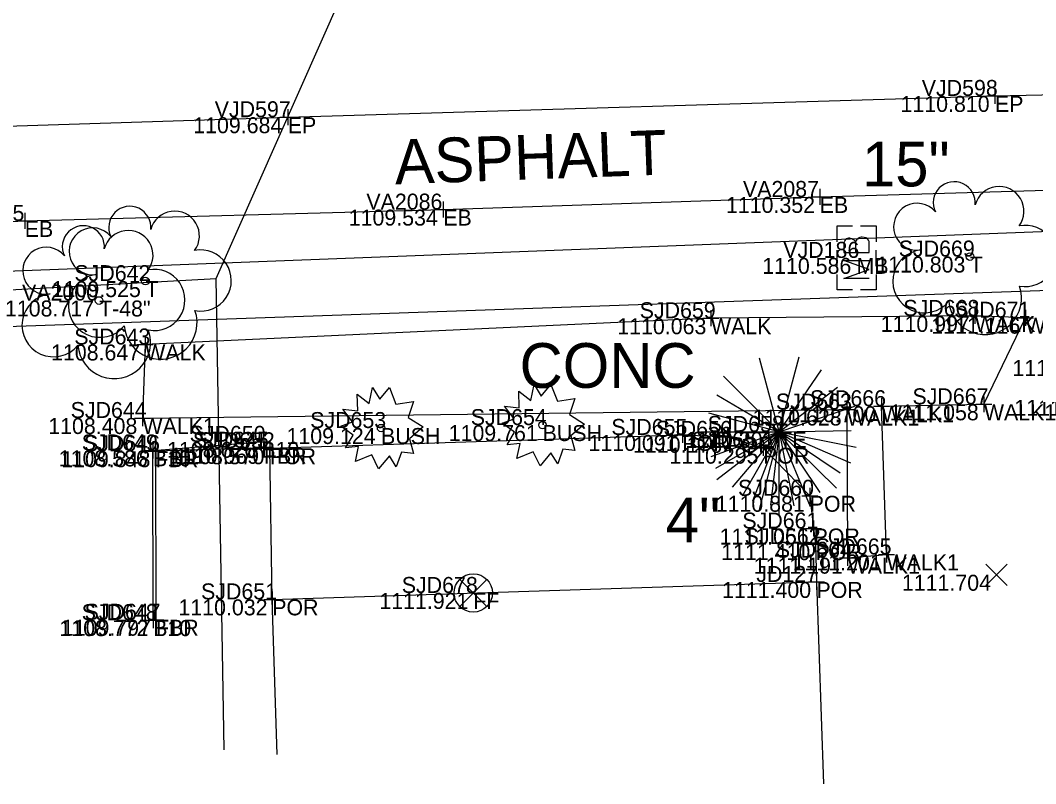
# Model space of a CAD drawing. Extents: x 1629915 to 1630675, y 484401 to 484601.
# Drawn here: x 1630425.3 to 1630488.9, y 484441.8 to 484489.5 of the extents above; entities that cross this region are included whole.
import ezdxf

# ---------------------------------------------------------------- set-up
doc = ezdxf.new("R2010")
doc.units = 0
for name, color, linetype in [('BD_X_Building', 7, 'Continuous'), ('BD_X_Porch_or_Deck', 7, 'Continuous'), ('BR_X_Sub_Foot_Object', 7, 'Continuous'), ('PV_X_EOP', 7, 'Continuous'), ('PV_X_Shoulder_Aggregate', 7, 'Continuous'), ('PV_X_Walk', 7, 'Continuous'), ('RD_X_Cells', 7, 'Continuous'), ('RD_X_RR_Cells', 7, 'Continuous'), ('SC_Scratch2', 7, 'Continuous'), ('SV_X_Break_Lines', 7, 'Continuous'), ('SV_X_Random_Point', 7, 'Continuous'), ('SV_X_Shot_Marker', 7, 'Continuous'), ('SV_X_Text_Comment', 7, 'Continuous'), ('SV_X_Text_Elevation', 7, 'Continuous'), ('SV_X_Text_Name', 7, 'Continuous'), ('TX_X_20', 7, 'Continuous'), ('UT_X_Gas', 7, 'Continuous'), ('UT_X_Water', 7, 'Continuous'), ('VG_X_Cells', 7, 'Continuous'), ('VG_X_Flower_Bed', 7, 'Continuous')]:
    doc.layers.add(name, color=color, linetype=linetype)

msp = doc.modelspace()

# ---------------------------------------------------------------- linework, layer by layer
at = {"layer": 'BD_X_Building'}
msp.add_lwpolyline([(1630441.402, 484443.574), (1630441.085, 484453.287), (1630475.163, 484454.377), (1630475.611, 484441.75)], dxfattribs=at)
at = {"layer": 'BD_X_Porch_or_Deck'}
msp.add_lwpolyline([(1630441.085, 484453.287), (1630440.931, 484462.744), (1630466.767, 484463.579), (1630469.583, 484463.459), (1630471.822, 484462.781), (1630474.739, 484459.77), (1630474.981, 484457.721), (1630475.11, 484456.743), (1630475.163, 484454.377)], dxfattribs=at)
at = {"layer": 'BR_X_Sub_Foot_Object'}
msp.add_line((1630334.981, 484467.226), (1630537.673, 484474.324), dxfattribs=at)
at = {"layer": 'PV_X_EOP'}
msp.add_lwpolyline([(1630292.708, 484478.565), (1630303.888, 484478.677), (1630360.908, 484480.855), (1630403.548, 484482.238), (1630442.06, 484483.465), (1630486.339, 484484.798), (1630529.418, 484485.732), (1630568.745, 484486.748), (1630610.183, 484487.853), (1630650.035, 484489.089)], dxfattribs=at)
at = {"layer": 'PV_X_Shoulder_Aggregate'}
msp.add_lwpolyline([(1630290.023, 484472.094), (1630316.065, 484472.69), (1630342.812, 484473.661), (1630368.021, 484474.923), (1630386.578, 484475.757), (1630401.756, 484475.856), (1630425.589, 484476.973), (1630451.796, 484477.683), (1630475.368, 484478.476), (1630505.195, 484479.358), (1630508.151, 484481.327), (1630508.061, 484484.385), (1630516.813, 484484.736), (1630516.951, 484481.103), (1630520.694, 484479.601), (1630540.986, 484479.176), (1630540.508, 484484.672), (1630564.841, 484485.646), (1630589.64, 484486.306), (1630613.109, 484486.832)], dxfattribs=at)
at = {"layer": 'PV_X_Walk'}
for p, q in [((1630468.554, 484470.882), (1630433.129, 484469.24)), ((1630485.08, 484471.029), (1630468.554, 484470.882)), ((1630488.254, 484470.917), (1630485.08, 484471.029)), ((1630485.646, 484465.495), (1630488.254, 484470.917)), ((1630433.129, 484469.24), (1630432.958, 484464.638))]:
    msp.add_line(p, q, dxfattribs=at)
msp.add_lwpolyline([(1630432.958, 484464.638), (1630477.064, 484465.169), (1630477.115, 484455.894), (1630479.551, 484456.099), (1630479.242, 484465.378), (1630485.646, 484465.495)], dxfattribs=at)
at = {"layer": 'RD_X_Cells'}
for p, q in [((1630476.45, 484474.15), (1630476.45, 484475.151)), ((1630478.893, 484474.15), (1630478.893, 484475.151)), ((1630477.671, 484474.661), (1630477.671, 484474.661))]:
    msp.add_line(p, q, dxfattribs=at)
for points in [[(1630476.45, 484475.668), (1630476.45, 484476.661), (1630477.42, 484476.661)], [(1630477.923, 484476.661), (1630478.893, 484476.661), (1630478.893, 484475.668)], [(1630477.602, 484475.683), (1630477.539, 484475.746), (1630477.501, 484475.784), (1630477.464, 484475.809), (1630477.438, 484475.821), (1630477.388, 484475.847), (1630477.35, 484475.859), (1630477.262, 484475.885), (1630477.224, 484475.885), (1630477.174, 484475.885), (1630477.098, 484475.872), (1630477.035, 484475.847), (1630476.985, 484475.809), (1630476.934, 484475.746), (1630476.909, 484475.695), (1630476.897, 484475.67), (1630476.871, 484475.607), (1630476.871, 484474.99), (1630478.471, 484474.99), (1630478.471, 484475.683), (1630478.421, 484475.771), (1630478.358, 484475.847), (1630478.257, 484475.91), (1630478.144, 484475.947), (1630478.03, 484475.96), (1630477.955, 484475.96), (1630477.879, 484475.935), (1630477.766, 484475.885), (1630477.69, 484475.821), (1630477.602, 484475.683), (1630477.602, 484474.99)], [(1630478.471, 484473.365), (1630476.871, 484473.365), (1630478.471, 484473.944), (1630476.871, 484474.499), (1630478.471, 484474.499)], [(1630477.42, 484472.661), (1630476.45, 484472.661), (1630476.45, 484473.631)], [(1630478.893, 484473.631), (1630478.893, 484472.661), (1630477.923, 484472.661)]]:
    msp.add_lwpolyline(points, dxfattribs=at)
at = {"layer": 'RD_X_RR_Cells'}
for p, q in [((1630454.521, 484452.841), (1630452.824, 484454.538)), ((1630452.824, 484452.841), (1630454.521, 484454.538))]:
    msp.add_line(p, q, dxfattribs=at)
msp.add_circle((1630453.673, 484453.689), 1.2, dxfattribs=at)
at = {"layer": 'SC_Scratch2'}
msp.add_circle((1630433.148, 484473.207), 0.24, dxfattribs=at)
for centre, radius, start, end in [((1630432.164, 484476.575), 1.317, 354.0047, 205.97412), ((1630434.974, 484476.036), 1.553, 323.82996, 165.0376), ((1630429.839, 484475.071), 1.471, 39.06254, 279.54124), ((1630436.608, 484473.243), 1.915, 259.14531, 101.45961), ((1630430.295, 484471.658), 1.974, 96.17219, 320.57371), ((1630434.095, 484470.602), 2.284, 184.94757, 19.45715)]:
    msp.add_arc(centre, radius, start, end, dxfattribs=at)
at = {"layer": 'SV_X_Break_Lines'}
msp.add_lwpolyline([(1630433.632, 484451.985), (1630433.618, 484462.612), (1630440.398, 484463.147)], dxfattribs=at)
at = {"layer": 'SV_X_Random_Point'}
for p, q in [((1630485.768, 484454.159), (1630487.101, 484455.494)), ((1630485.768, 484455.494), (1630487.101, 484454.159))]:
    msp.add_line(p, q, dxfattribs=at)
at = {"layer": 'SV_X_Shot_Marker'}
for p, q in [((1630486.339, 484485.298), (1630486.339, 484484.298)), ((1630485.839, 484484.798), (1630486.839, 484484.798)), ((1630486.339, 484484.798), (1630486.339, 484484.798)), ((1630442.06, 484483.965), (1630442.06, 484482.965)), ((1630441.56, 484483.465), (1630442.56, 484483.465)), ((1630442.06, 484483.465), (1630442.06, 484483.465)), ((1630475.368, 484478.976), (1630475.368, 484477.976)), ((1630451.796, 484478.183), (1630451.796, 484477.183)), ((1630474.868, 484478.476), (1630475.868, 484478.476)), ((1630475.368, 484478.476), (1630475.368, 484478.476)), ((1630425.589, 484477.473), (1630425.589, 484476.473)), ((1630451.296, 484477.683), (1630452.296, 484477.683)), ((1630451.796, 484477.683), (1630451.796, 484477.683)), ((1630425.089, 484476.973), (1630426.089, 484476.973)), ((1630425.589, 484476.973), (1630425.589, 484476.973)), ((1630485.08, 484471.529), (1630485.08, 484470.529)), ((1630468.054, 484470.882), (1630469.054, 484470.882)), ((1630468.554, 484471.382), (1630468.554, 484470.382)), ((1630468.554, 484470.882), (1630468.554, 484470.882)), ((1630484.58, 484471.029), (1630485.58, 484471.029)), ((1630485.08, 484471.029), (1630485.08, 484471.029)), ((1630487.754, 484470.917), (1630488.754, 484470.917)), ((1630488.254, 484471.417), (1630488.254, 484470.417)), ((1630488.254, 484470.917), (1630488.254, 484470.917)), ((1630433.129, 484469.74), (1630433.129, 484468.74)), ((1630432.629, 484469.24), (1630433.629, 484469.24)), ((1630433.129, 484469.24), (1630433.129, 484469.24)), ((1630479.242, 484465.878), (1630479.242, 484464.878)), ((1630485.646, 484465.995), (1630485.646, 484464.995)), ((1630476.564, 484465.169), (1630477.564, 484465.169)), ((1630477.064, 484465.669), (1630477.064, 484464.669)), ((1630477.064, 484465.169), (1630477.064, 484465.169)), ((1630478.742, 484465.378), (1630479.742, 484465.378)), ((1630479.242, 484465.378), (1630479.242, 484465.378)), ((1630485.146, 484465.495), (1630486.146, 484465.495)), ((1630485.646, 484465.495), (1630485.646, 484465.495)), ((1630432.458, 484464.638), (1630433.458, 484464.638)), ((1630432.958, 484465.138), (1630432.958, 484464.138)), ((1630432.958, 484464.638), (1630432.958, 484464.638)), ((1630466.767, 484464.079), (1630466.767, 484463.079)), ((1630469.583, 484463.959), (1630469.583, 484462.959)), ((1630440.398, 484463.647), (1630440.398, 484462.647)), ((1630440.563, 484463.275), (1630440.563, 484462.275)), ((1630440.931, 484463.244), (1630440.931, 484462.244)), ((1630466.267, 484463.579), (1630467.267, 484463.579)), ((1630466.767, 484463.579), (1630466.767, 484463.579)), ((1630469.083, 484463.459), (1630470.083, 484463.459)), ((1630469.583, 484463.459), (1630469.583, 484463.459)), ((1630471.822, 484463.281), (1630471.822, 484462.281)), ((1630433.118, 484462.612), (1630434.118, 484462.612)), ((1630433.618, 484463.112), (1630433.618, 484462.112)), ((1630433.618, 484462.612), (1630433.618, 484462.612)), ((1630433.777, 484463.061), (1630433.777, 484462.061)), ((1630439.898, 484463.147), (1630440.898, 484463.147)), ((1630440.063, 484462.775), (1630441.063, 484462.775)), ((1630440.398, 484463.147), (1630440.398, 484463.147)), ((1630440.431, 484462.744), (1630441.431, 484462.744)), ((1630440.563, 484462.775), (1630440.563, 484462.775)), ((1630440.931, 484462.744), (1630440.931, 484462.744)), ((1630471.322, 484462.781), (1630472.322, 484462.781)), ((1630471.822, 484462.781), (1630471.822, 484462.781)), ((1630433.277, 484462.561), (1630434.277, 484462.561)), ((1630433.777, 484462.561), (1630433.777, 484462.561)), ((1630474.739, 484460.27), (1630474.739, 484459.27)), ((1630474.239, 484459.77), (1630475.239, 484459.77)), ((1630474.739, 484459.77), (1630474.739, 484459.77)), ((1630474.981, 484458.221), (1630474.981, 484457.221)), ((1630474.481, 484457.721), (1630475.481, 484457.721)), ((1630474.981, 484457.721), (1630474.981, 484457.721)), ((1630475.11, 484457.243), (1630475.11, 484456.243)), ((1630474.61, 484456.743), (1630475.61, 484456.743)), ((1630475.11, 484456.743), (1630475.11, 484456.743)), ((1630477.115, 484456.394), (1630477.115, 484455.394)), ((1630479.551, 484456.599), (1630479.551, 484455.599)), ((1630476.615, 484455.894), (1630477.615, 484455.894)), ((1630477.115, 484455.894), (1630477.115, 484455.894)), ((1630479.051, 484456.099), (1630480.051, 484456.099)), ((1630479.551, 484456.099), (1630479.551, 484456.099)), ((1630474.663, 484454.377), (1630475.663, 484454.377)), ((1630475.163, 484454.877), (1630475.163, 484453.877)), ((1630475.163, 484454.377), (1630475.163, 484454.377)), ((1630441.085, 484453.787), (1630441.085, 484452.787)), ((1630440.585, 484453.287), (1630441.585, 484453.287)), ((1630441.085, 484453.287), (1630441.085, 484453.287)), ((1630433.632, 484452.485), (1630433.632, 484451.485)), ((1630433.807, 484452.512), (1630433.807, 484451.512)), ((1630433.132, 484451.985), (1630434.132, 484451.985)), ((1630433.307, 484452.012), (1630434.307, 484452.012)), ((1630433.632, 484451.985), (1630433.632, 484451.985)), ((1630433.807, 484452.012), (1630433.807, 484452.012))]:
    msp.add_line(p, q, dxfattribs=at)
at = {"layer": 'UT_X_Gas'}
for p, q in [((1630437.584, 484473.366), (1630453.173, 484508.545)), ((1630362.604, 484469.23), (1630437.584, 484473.366)), ((1630438.082, 484443.865), (1630437.584, 484473.366))]:
    msp.add_line(p, q, dxfattribs=at)
at = {"layer": 'UT_X_Water'}
msp.add_line((1630348.219, 484470.927), (1630675.08, 484483.409), dxfattribs=at)
at = {"layer": 'VG_X_Cells'}
for p, q in [((1630472.832, 484463.769), (1630471.597, 484468.382)), ((1630472.832, 484463.769), (1630474.088, 484468.467)), ((1630472.832, 484463.769), (1630469.342, 484467.256)), ((1630472.832, 484463.769), (1630475.487, 484467.654)), ((1630472.832, 484463.769), (1630476.488, 484466.574)), ((1630472.832, 484463.769), (1630468.925, 484466.066)), ((1630472.832, 484463.769), (1630477.568, 484465.376)), ((1630472.832, 484463.769), (1630468.418, 484464.952)), ((1630467.897, 484463.769), (1630472.832, 484463.769)), ((1630472.832, 484463.769), (1630468.542, 484462.207)), ((1630472.832, 484463.769), (1630468.848, 484461.487)), ((1630472.832, 484463.769), (1630468.925, 484460.774)), ((1630472.832, 484463.769), (1630469.887, 484460.302)), ((1630472.832, 484463.769), (1630470.513, 484459.754)), ((1630472.832, 484463.769), (1630471.167, 484459.429)), ((1630472.832, 484463.769), (1630471.568, 484458.912)), ((1630472.832, 484463.769), (1630472.29, 484459.177)), ((1630472.832, 484463.769), (1630477.342, 484463.861)), ((1630472.832, 484458.529), (1630472.832, 484463.769)), ((1630472.832, 484463.769), (1630473.753, 484459.132)), ((1630472.832, 484463.769), (1630474.765, 484459.101)), ((1630472.832, 484463.769), (1630475.368, 484459.976)), ((1630472.832, 484463.769), (1630476.42, 484460.247)), ((1630472.832, 484463.769), (1630476.653, 484461.214)), ((1630472.832, 484463.769), (1630477.297, 484461.827)), ((1630472.832, 484463.769), (1630477.66, 484462.811))]:
    msp.add_line(p, q, dxfattribs=at)
for points in [[(1630447.814, 484465.821), (1630448.419, 484466.556), (1630448.834, 484465.502), (1630449.926, 484465.682), (1630449.588, 484464.671), (1630450.533, 484464.076), (1630449.676, 484463.341), (1630449.926, 484462.427), (1630449.173, 484462.496), (1630448.848, 484461.582), (1630448.419, 484462.274), (1630447.741, 484461.457), (1630447.313, 484462.344), (1630446.293, 484461.914), (1630446.484, 484462.856), (1630445.673, 484462.772), (1630446.146, 484463.562), (1630445.378, 484464.131), (1630446.116, 484464.394), (1630445.509, 484465.197), (1630446.441, 484465.087), (1630446.411, 484466.126), (1630447.164, 484465.557), (1630447.371, 484466.542), (1630447.814, 484465.821)], [(1630457.93, 484466.006), (1630458.535, 484466.741), (1630458.95, 484465.687), (1630460.042, 484465.867), (1630459.703, 484464.856), (1630460.648, 484464.261), (1630459.792, 484463.526), (1630460.042, 484462.612), (1630459.288, 484462.681), (1630458.963, 484461.767), (1630458.535, 484462.459), (1630457.857, 484461.642), (1630457.428, 484462.529), (1630456.408, 484462.099), (1630456.6, 484463.041), (1630455.788, 484462.957), (1630456.262, 484463.747), (1630455.493, 484464.316), (1630456.232, 484464.579), (1630455.625, 484465.382), (1630456.557, 484465.272), (1630456.527, 484466.311), (1630457.28, 484465.742), (1630457.487, 484466.727), (1630457.93, 484466.006)]]:
    msp.add_lwpolyline(points, dxfattribs=at)
for centre, radius in [((1630484.774, 484474.745), 0.24), ((1630430.243, 484471.993), 0.24), ((1630447.899, 484464.011), 0.23), ((1630458.014, 484464.196), 0.23)]:
    msp.add_circle(centre, radius, dxfattribs=at)
for centre, radius, start, end in [((1630483.791, 484478.112), 1.317, 354.0047, 205.97412), ((1630486.6, 484477.574), 1.553, 323.82996, 165.0376), ((1630481.465, 484476.609), 1.471, 39.06254, 279.54124), ((1630429.259, 484475.36), 1.317, 354.0047, 205.97412), ((1630488.235, 484474.781), 1.915, 259.14531, 101.45961), ((1630432.069, 484474.822), 1.553, 323.82996, 165.0376), ((1630426.934, 484473.857), 1.471, 39.06254, 279.54124), ((1630481.921, 484473.196), 1.974, 96.17219, 320.57371), ((1630433.703, 484472.029), 1.915, 259.14531, 101.45961), ((1630485.721, 484472.14), 2.284, 184.94757, 19.45715), ((1630427.39, 484470.444), 1.974, 96.17219, 320.57371), ((1630431.189, 484469.387), 2.284, 184.94757, 19.45715)]:
    msp.add_arc(centre, radius, start, end, dxfattribs=at)
at = {"layer": 'VG_X_Flower_Bed'}
msp.add_lwpolyline([(1630440.563, 484462.775), (1630433.777, 484462.561), (1630433.807, 484452.012)], dxfattribs=at)

# ---------------------------------------------------------------- texts
at = {"layer": 'SV_X_Text_Comment'}
for s, p in [('EP', (1630486.339, 484483.798)), ('EP', (1630442.06, 484482.465)), ('EB', (1630475.368, 484477.476)), ('EB', (1630451.796, 484476.683)), ('EB', (1630425.589, 484475.973)), ('T', (1630484.774, 484473.745)), ('MB', (1630477.671, 484473.661)), ('T', (1630433.148, 484472.207)), ('T-48"', (1630430.243, 484470.993)), ('WALK', (1630468.554, 484469.882)), ('WALK', (1630485.08, 484470.029)), ('WALK', (1630488.254, 484469.917)), ('WALK', (1630433.129, 484468.24)), ('WALK1', (1630477.064, 484464.169)), ('WALK1', (1630479.242, 484464.378)), ('WALK1', (1630485.646, 484464.495)), ('WALK1', (1630432.958, 484463.638)), ('BUSH', (1630447.899, 484463.011)), ('BUSH', (1630458.015, 484463.196)), ('POR', (1630466.767, 484462.579)), ('POR', (1630469.583, 484462.459)), ('TE', (1630472.832, 484462.769)), ('B10', (1630433.618, 484461.612)), ('B10', (1630440.398, 484462.147)), ('FBR', (1630440.563, 484461.775)), ('POR', (1630440.931, 484461.744)), ('POR', (1630471.822, 484461.781)), ('FBR', (1630433.777, 484461.561)), ('POR', (1630474.739, 484458.77)), ('POR', (1630474.981, 484456.721)), ('POR', (1630475.11, 484455.743)), ('WALK1', (1630477.115, 484454.894)), ('WALK1', (1630479.551, 484455.099)), ('POR', (1630475.163, 484453.377)), ('POR', (1630441.085, 484452.287)), ('FF', (1630453.673, 484452.689)), ('B10', (1630433.632, 484450.985)), ('FBR', (1630433.807, 484451.012))]:
    msp.add_text(s, height=1, dxfattribs=at).set_placement(p)
at = {"layer": 'SV_X_Text_Elevation'}
for s, p in [('1110.810', (1630480.428, 484483.798)), ('1109.684', (1630436.139, 484482.465)), ('1110.352', (1630469.497, 484477.476)), ('1109.534', (1630445.876, 484476.683)), ('1110.803', (1630478.912, 484473.745)), ('1110.586', (1630471.769, 484473.661)), ('1109.525', (1630427.28, 484472.207)), ('1108.717', (1630424.349, 484470.993)), ('1110.063', (1630462.692, 484469.882)), ('1110.997', (1630479.187, 484470.029)), ('1111.116', (1630482.351, 484469.917)), ('1108.647', (1630427.235, 484468.24)), ('1111.342', (1630487.434, 484467.273)), ('1111.404', (1630487.556, 484464.775)), ('1110.628', (1630471.165, 484464.169)), ('1110.700', (1630473.331, 484464.378)), ('1111.058', (1630479.748, 484464.495)), ('1108.408', (1630427.06, 484463.638)), ('1109.124', (1630441.979, 484463.011)), ('1109.761', (1630452.135, 484463.196)), ('1110.091', (1630460.887, 484462.579)), ('1110.176', (1630463.68, 484462.459)), ('1110.301', (1630466.952, 484462.769)), ('1108.586', (1630427.716, 484461.612)), ('1108.626', (1630434.496, 484462.147)), ('1110.069', (1630434.681, 484461.775)), ('1108.570', (1630435.02, 484461.744)), ('1110.295', (1630465.953, 484461.781)), ('1109.848', (1630427.878, 484461.561)), ('1110.881', (1630468.859, 484458.77)), ('1111.051', (1630469.101, 484456.721)), ('1111.410', (1630469.198, 484455.743)), ('1111.191', (1630471.235, 484454.894)), ('1111.201', (1630473.672, 484455.099)), ('1111.400', (1630469.251, 484453.377)), ('1111.704', (1630480.514, 484453.827)), ('1110.032', (1630435.213, 484452.287)), ('1111.921', (1630447.793, 484452.689)), ('1108.772', (1630427.76, 484450.985)), ('1109.797', (1630427.913, 484451.012))]:
    msp.add_text(s, height=1, dxfattribs=at).set_placement(p)
at = {"layer": 'SV_X_Text_Name'}
for s, p in [('VJD598', (1630481.759, 484484.798)), ('VJD597', (1630437.484, 484483.465)), ('VA2087', (1630470.561, 484478.476)), ('VA2086', (1630446.981, 484477.683)), ('VA2085', (1630420.808, 484476.973)), ('VJD186', (1630473.087, 484474.661)), ('SJD669', (1630480.316, 484474.745)), ('SJD642', (1630428.7, 484473.207)), ('VA2000', (1630425.419, 484471.993)), ('SJD659', (1630464.095, 484470.882)), ('SJD668', (1630480.605, 484471.029)), ('SJD671', (1630483.797, 484470.917)), ('SJD643', (1630428.691, 484469.24)), ('SJD667', (1630481.176, 484465.495)), ('SJD663', (1630472.625, 484465.169)), ('SJD666', (1630474.763, 484465.378)), ('SJD644', (1630428.462, 484464.638)), ('SJD654', (1630453.518, 484464.196)), ('SJD653', (1630443.461, 484464.011)), ('SJD655', (1630462.322, 484463.579)), ('SJD658', (1630468.357, 484463.769)), ('SJD650', (1630435.91, 484463.147)), ('SJD656', (1630465.104, 484463.459)), ('SJD649', (1630429.16, 484462.612)), ('SJD646', (1630429.298, 484462.561)), ('SJD645', (1630436.118, 484462.775)), ('SJD652', (1630436.483, 484462.744)), ('SJD657', (1630467.351, 484462.781)), ('SJD660', (1630470.251, 484459.77)), ('SJD661', (1630470.525, 484457.721)), ('SJD662', (1630470.662, 484456.743)), ('SJD664', (1630472.618, 484455.894)), ('SJD665', (1630475.106, 484456.099)), ('JD127', (1630471.399, 484454.377)), ('SJD678', (1630449.198, 484453.689)), ('SJD651', (1630436.628, 484453.287)), ('SJD648', (1630429.156, 484451.985)), ('SJD647', (1630429.336, 484452.012))]:
    msp.add_text(s, height=1, dxfattribs=at).set_placement(p)
at = {"layer": 'TX_X_20'}
msp.add_text('ASPHALT', height=2.8, rotation=2.08045, dxfattribs=at).set_placement((1630448.788, 484479.262))
for s, p in [('15"', (1630478.013, 484479.135)), ('CONC', (1630456.573, 484466.526)), ('4"', (1630465.729, 484456.858))]:
    msp.add_text(s, height=2.8, dxfattribs=at).set_placement(p)

doc.saveas('drawing.dxf')
